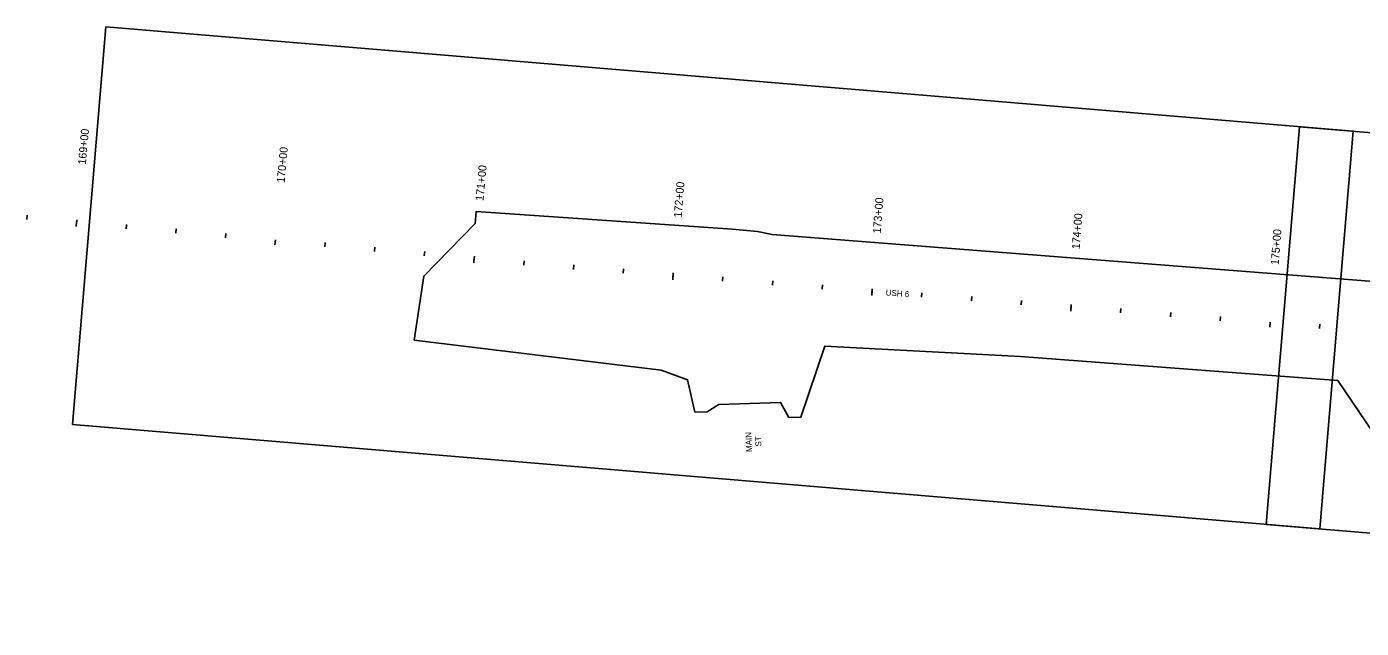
# Model space of a CAD drawing. Extents: x 20499876 to 20505320, y 7953544 to 7954108.
# Drawn here: x 20500588 to 20501256, y 7953788 to 7954090 of the extents above; entities that cross this region are included whole.
import ezdxf

# ---------------------------------------------------------------- set-up
doc = ezdxf.new("R2010")
doc.units = 0
for name, color, linetype in [('Draft_0', 7, 'Continuous'), ('Draft_7', 7, 'Continuous'), ('Drainage- Pipe', 7, 'Continuous'), ('PS_CONST', 7, 'Continuous'), ('Wall', 7, 'Continuous')]:
    doc.layers.add(name, color=color, linetype=linetype)

msp = doc.modelspace()

# ---------------------------------------------------------------- linework, layer by layer
at = {"layer": 'Draft_7'}
for p, q in [((20500587.68, 7953992.96), (20500587.87, 7953995.14)), ((20500612.68, 7953991.91), (20500612.46, 7953989.47)), ((20500637.47, 7953988.41), (20500637.67, 7953990.58)), ((20500662.36, 7953986.13), (20500662.56, 7953988.3)), ((20500687.26, 7953983.85), (20500687.46, 7953986.03)), ((20500712.27, 7953982.79), (20500712.04, 7953980.35)), ((20500737.05, 7953979.29), (20500737.25, 7953981.47)), ((20500761.95, 7953977.02), (20500762.15, 7953979.19)), ((20500786.84, 7953974.74), (20500787.04, 7953976.91)), ((20500811.85, 7953973.68), (20500811.63, 7953971.24)), ((20500836.64, 7953970.18), (20500836.83, 7953972.36)), ((20500861.54, 7953968.04), (20500861.72, 7953970.22)), ((20500886.46, 7953966.06), (20500886.64, 7953968.24)), ((20500911.48, 7953965.3), (20500911.29, 7953962.86)), ((20500936.31, 7953962.1), (20500936.48, 7953964.28)), ((20500961.23, 7953960.12), (20500961.4, 7953962.3)), ((20500986.15, 7953958.14), (20500986.32, 7953960.31)), ((20501011.17, 7953957.38), (20501010.97, 7953954.94)), ((20501035.99, 7953954.18), (20501036.17, 7953956.35)), ((20501060.91, 7953952.2), (20501061.09, 7953954.37)), ((20501085.84, 7953950.22), (20501086.01, 7953952.39)), ((20501110.85, 7953949.46), (20501110.66, 7953947.02)), ((20501135.68, 7953946.26), (20501135.85, 7953948.43)), ((20501160.6, 7953944.27), (20501160.77, 7953946.45)), ((20501185.52, 7953942.29), (20501185.69, 7953944.47)), ((20501210.54, 7953941.53), (20501210.35, 7953939.09)), ((20501235.36, 7953938.33), (20501235.54, 7953940.51))]:
    msp.add_line(p, q, dxfattribs=at)
at = {"layer": 'Drainage- Pipe'}
for points in [[(20500627.39, 7954089.64), (20500610.68, 7953890.34), (20501235.48, 7953837.95), (20501252.19, 7954037.25)], [(20501225.23, 7954039.5), (20501208.63, 7953840.19), (20501833.46, 7953788.16), (20501850.06, 7953987.47)]]:
    msp.add_lwpolyline(points, close=True, dxfattribs=at)
at = {"layer": 'PS_CONST'}
for p, q in [((20500612.57, 7953990.69), (20500612.77, 7953992.86)), ((20500712.27, 7953982.79), (20500712.04, 7953980.35)), ((20500811.74, 7953972.46), (20500811.94, 7953974.64)), ((20500911.39, 7953964.08), (20500911.56, 7953966.26)), ((20501011.07, 7953956.16), (20501011.24, 7953958.33)), ((20501110.76, 7953948.24), (20501110.93, 7953950.41)), ((20501210.54, 7953941.53), (20501210.35, 7953939.09))]:
    msp.add_line(p, q, dxfattribs=at)
at = {"layer": 'Wall'}
msp.add_lwpolyline([(20501261.93, 7953886.46), (20501244.4, 7953912.4), (20501085.46, 7953924.44), (20500987.46, 7953929.51), (20500975.54, 7953894.02), (20500969.49, 7953893.86), (20500965.3, 7953901.35), (20500934.39, 7953900.27), (20500928.56, 7953896.65), (20500922.42, 7953896.4), (20500918.72, 7953912.73), (20500905.46, 7953917.46), (20500781.85, 7953932.48), (20500786.55, 7953964.7), (20500812.3, 7953991.06), (20500812.66, 7953994.97), (20500812.81, 7953996.95), (20500941.31, 7953988.1), (20500953.71, 7953986.99), (20500961.05, 7953985.49), (20501585.27, 7953936.81)], dxfattribs=at)

# ---------------------------------------------------------------- texts
at = {"layer": 'Draft_0'}
for s, rotation, p in [('USH 6', 355, (20501017.89, 7953955.05)), ('MAIN', 91.87706, (20500951.02, 7953876.55)), ('ST', 91.87706, (20500955.73, 7953879.27))]:
    msp.add_text(s, height=3, rotation=rotation, dxfattribs=at).set_placement(p)
at = {"layer": 'Draft_7'}
for s, rotation, p in [('169+00', 84.77145, (20500617.3, 7954020.38)), ('170+00', 84.77145, (20500716.88, 7954011.27)), ('171+00', 84.77145, (20500816.47, 7954002.15)), ('172+00', 85.45642, (20500915.76, 7953993.83)), ('173+00', 85.45642, (20501015.45, 7953985.9)), ('174+00', 85.45642, (20501115.13, 7953977.98)), ('175+00', 85.45642, (20501214.82, 7953970.06))]:
    msp.add_text(s, height=4.008, rotation=rotation, dxfattribs=at).set_placement(p)
at = {"layer": 'PS_CONST'}
for s, rotation, p in [('170+00', 84.77145, (20500716.88, 7954011.27)), ('175+00', 85.45642, (20501214.82, 7953970.06))]:
    msp.add_text(s, height=4.008, rotation=rotation, dxfattribs=at).set_placement(p)

doc.saveas('drawing.dxf')
